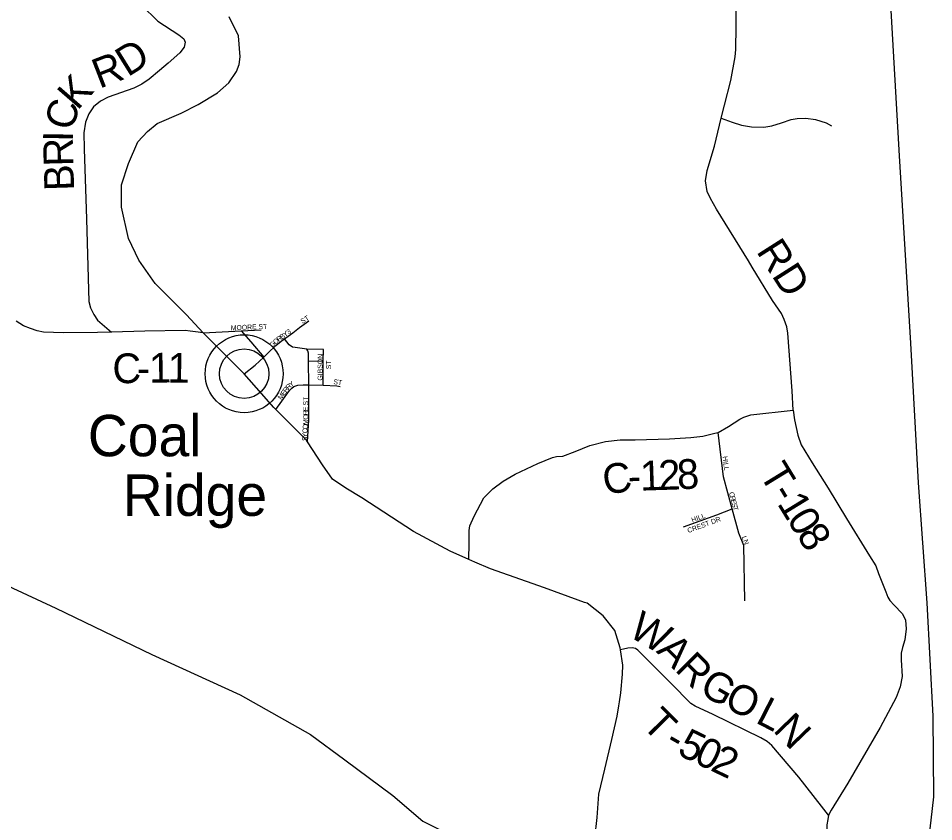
# Model space of a CAD drawing. Extents: x -22 to 431, y -18 to 160.
# Drawn here: x 322.192 to 323.94, y 149.867 to 151.4 of the extents above; entities that cross this region are included whole.
import ezdxf

# ---------------------------------------------------------------- set-up
doc = ezdxf.new("R2010")
doc.units = 0
for name, color, linetype in [('GM_X_Adjacent_County', 7, 'Continuous'), ('GM_X_Adjacent_County_Text', 7, 'Continuous'), ('GM_X_City_Street', 7, 'Continuous'), ('GM_X_City_Street_Text', 7, 'Continuous'), ('GM_X_County_Road', 7, 'Continuous'), ('GM_X_County_ROW', 7, 'Continuous'), ('GM_X_County_Subdivision', 7, 'Continuous'), ('GM_X_Minor_River_Text', 7, 'Continuous'), ('GM_X_Rail_Line', 7, 'Continuous'), ('GM_X_Township_Road', 7, 'Continuous'), ('GM_X_Township_ROW', 7, 'Continuous')]:
    doc.layers.add(name, color=color, linetype=linetype)

msp = doc.modelspace()

# ---------------------------------------------------------------- linework, layer by layer
at = {"layer": 'GM_X_Adjacent_County_Text'}
for points in [[(323.5933, 150.9254), (323.586, 150.9372), (323.525, 151.0361), (323.5136, 151.0562), (323.5075, 151.0698), (323.5045, 151.0903), (323.5075, 151.1097), (323.5211, 151.1564), (323.5344, 151.2095), (323.5407, 151.2346), (323.5524, 151.2816), (323.5607, 151.3268), (323.5622, 151.3408), (323.5629, 151.3848), (323.5629, 151.4307)], [(323.6719, 150.6523), (323.6696, 150.6895), (323.6611, 150.7992), (323.6592, 150.8117), (323.6543, 150.8253), (323.6494, 150.8371), (323.6323, 150.8617), (323.5933, 150.9254)], [(322.5453, 150.8003), (322.5304, 150.8018), (322.5202, 150.8031), (322.5107, 150.8045), (322.4338, 150.8031), (322.3702, 150.8016), (322.3437, 150.8007), (322.2785, 150.7999), (322.2402, 150.8015), (322.2285, 150.8036), (322.2155, 150.8083), (322.2022, 150.8134), (322.188, 150.8226)], [(323.0523, 150.3676), (323.053, 150.3987), (323.0533, 150.423), (323.0541, 150.4318), (323.0624, 150.4504), (323.0813, 150.4853), (323.098, 150.5024), (323.118, 150.5172), (323.1411, 150.5301), (323.1839, 150.5507), (323.2123, 150.5621), (323.2198, 150.564), (323.2319, 150.5648), (323.2554, 150.5736), (323.2834, 150.585), (323.3133, 150.5926), (323.3414, 150.5961), (323.3698, 150.5961), (323.4353, 150.5977), (323.4765, 150.6005), (323.4993, 150.6028), (323.522, 150.6085), (323.5282, 150.6098), (323.5481, 150.6211), (323.5697, 150.6351), (323.5772, 150.6393), (323.5905, 150.6435), (323.6719, 150.6523)]]:
    msp.add_lwpolyline(points, dxfattribs=at)
at = {"layer": 'GM_X_County_Road'}
msp.add_lwpolyline([(323.5344, 151.2095), (323.5553, 151.2023), (323.5731, 151.1964), (323.592, 151.1931), (323.6159, 151.1925), (323.6306, 151.1953), (323.6492, 151.2008), (323.6677, 151.207), (323.6794, 151.209), (323.696, 151.2095), (323.7142, 151.2073), (323.7343, 151.201), (323.7446, 151.1947)], dxfattribs=at)
at = {"layer": 'GM_X_County_ROW'}
for points in [[(323.2735, 150.2855), (323.2609, 150.2901), (323.1969, 150.3135), (323.0935, 150.3494), (323.0637, 150.3626), (323.0523, 150.3676), (323.0171, 150.3832), (322.9468, 150.4209), (322.8482, 150.4853), (322.8174, 150.5034), (322.7923, 150.5208), (322.7732, 150.5484), (322.7443, 150.5919), (322.7423, 150.595), (322.684, 150.6539), (322.6802, 150.6577), (322.6235, 150.722), (322.5539, 150.7912), (322.5453, 150.8003), (322.5133, 150.8343), (322.4539, 150.894), (322.4223, 150.9387), (322.4027, 150.98), (322.3892, 151.0396), (322.3891, 151.0825), (322.4029, 151.1232), (322.4207, 151.1642), (322.4388, 151.1843), (322.4574, 151.1992), (322.5035, 151.2191), (322.5354, 151.2357), (322.5724, 151.2578), (322.5944, 151.2768), (322.6088, 151.2988), (322.6141, 151.3121), (322.6159, 151.3265), (322.6129, 151.3667), (322.595, 151.4031)], [(322.1172, 150.3424), (322.2643, 150.2747), (322.4472, 150.1863), (322.6156, 150.1093), (322.7502, 150.0336), (322.816, 149.9854), (322.9073, 149.9171), (322.9648, 149.8683), (323.0568, 149.8221), (323.0865, 149.8101), (323.1193, 149.7957), (323.1226, 149.7951), (323.2065, 149.7788), (323.2897, 149.7606)], [(323.3389, 150.0883), (323.3401, 150.0961), (323.3426, 150.1129), (323.3455, 150.1486), (323.3462, 150.1661), (323.342, 150.1951), (323.3415, 150.1991), (323.3311, 150.2321), (323.3086, 150.2597), (323.2782, 150.2839), (323.2735, 150.2855)], [(323.2905, 149.7801), (323.2928, 149.8358), (323.2972, 149.8753), (323.3008, 149.9197), (323.312, 149.9676), (323.3255, 150.0243), (323.3359, 150.0684), (323.3389, 150.0883)]]:
    msp.add_lwpolyline(points, dxfattribs=at)
at = {"layer": 'GM_X_Minor_River_Text'}
for points in [[(322.4277, 151.4253), (322.4589, 151.3948), (322.4987, 151.3686), (322.5083, 151.3608), (322.5111, 151.3544), (322.509, 151.3452), (322.5009, 151.3344), (322.4785, 151.3143), (322.4617, 151.3007), (322.4423, 151.2841), (322.4284, 151.2743), (322.413, 151.2668), (322.4128, 151.2667)], [(322.4128, 151.2667), (322.3641, 151.25), (322.3495, 151.2418), (322.3356, 151.2313), (322.3271, 151.2178), (322.3206, 151.2022), (322.3172, 151.1816), (322.3181, 151.1509), (322.3223, 151.017), (322.3269, 150.8599), (322.3302, 150.8478), (322.3365, 150.8347), (322.3438, 150.8242), (322.3702, 150.8016)], [(323.6719, 150.6523), (323.6742, 150.6341), (323.6806, 150.6049), (323.6867, 150.5864), (323.7079, 150.5519), (323.7387, 150.5037), (323.7736, 150.4457), (323.8175, 150.3748), (323.8293, 150.3551), (323.8346, 150.3407), (323.8487, 150.3058), (323.8525, 150.2956), (323.8559, 150.2895), (323.8646, 150.2804), (323.8794, 150.2645), (323.8838, 150.2573), (323.8858, 150.252), (323.887, 150.235), (323.8847, 150.2141), (323.8806, 150.1997), (323.8779, 150.1887), (323.8776, 150.1758), (323.8795, 150.1443), (323.8757, 150.1245), (323.8685, 150.1044), (323.8375, 150.0467), (323.7759, 149.9404), (323.7441, 149.8895), (323.7392, 149.8797)], [(323.7392, 149.8797), (323.7256, 149.8971), (323.6824, 149.952), (323.6308, 150.0127), (323.6221, 150.0202), (323.61, 150.0274), (323.5187, 150.0717), (323.4842, 150.0876), (323.4762, 150.0929), (323.4383, 150.1315), (323.3997, 150.1698), (323.375, 150.1948), (323.3709, 150.1978), (323.3644, 150.1989), (323.3561, 150.1985), (323.342, 150.1951)], [(323.7392, 149.8797), (323.7377, 149.8713), (323.7358, 149.8615), (323.7351, 149.8387), (323.7321, 149.8091), (323.7298, 149.8008), (323.7284, 149.7951), (323.7272, 149.7875), (323.7268, 149.7583), (323.7266, 149.7514), (323.7213, 149.5557)]]:
    msp.add_lwpolyline(points, dxfattribs=at)
at = {"layer": 'GM_X_Rail_Line'}
msp.add_lwpolyline([(323.7541, 149.3438), (323.7718, 149.3859), (323.8142, 149.4956), (323.8253, 149.5261), (323.8788, 149.6629), (323.8836, 149.6785), (323.906, 149.7408), (323.9176, 149.7784), (323.9303, 149.8316), (323.9399, 149.9149), (323.9389, 150.0683), (323.9274, 150.2851), (323.911, 150.5141), (323.8962, 150.7806), (323.8747, 151.1376), (323.8507, 151.5599)], dxfattribs=at)
at = {"layer": 'GM_X_Township_Road'}
for radius in [0.0744, 0.0472]:
    msp.add_circle((322.6235, 150.722), radius, dxfattribs=at)
at = {"layer": 'GM_X_Township_ROW'}
for points in [[(322.6235, 150.722), (322.6443, 150.7382), (322.661, 150.7537), (322.6695, 150.7616), (322.6842, 150.7761), (322.694, 150.7841), (322.7004, 150.7888), (322.703, 150.7907), (322.7166, 150.7999), (322.7294, 150.8102), (322.7471, 150.8229)], [(322.5453, 150.8003), (322.6177, 150.8039), (322.6563, 150.8059)], [(322.6177, 150.8039), (322.6364, 150.7829), (322.661, 150.7537)], [(322.7443, 150.5919), (322.747, 150.6339), (322.7467, 150.7007), (322.7465, 150.7452), (322.7464, 150.761), (322.7453, 150.7659), (322.7433, 150.7686), (322.721, 150.7718), (322.7157, 150.7725), (322.7096, 150.7771), (322.7004, 150.7888)], [(322.7742, 150.6999), (322.7746, 150.7459), (322.7748, 150.7681), (322.7433, 150.7686)], [(322.7746, 150.7459), (322.7465, 150.7452)], [(322.684, 150.6539), (322.7102, 150.6902), (322.7143, 150.6944), (322.7185, 150.6978), (322.7257, 150.7001), (322.7359, 150.701), (322.7395, 150.7009)], [(322.7395, 150.7009), (322.7397, 150.7009), (322.7467, 150.7007), (322.7742, 150.6999), (322.8003, 150.6992), (322.8071, 150.6977)], [(323.5791, 150.2884), (323.5773, 150.3939), (323.5679, 150.4178), (323.5552, 150.4643), (323.5386, 150.525), (323.5282, 150.6098)], [(323.4625, 150.43), (323.5257, 150.453), (323.5552, 150.4643)]]:
    msp.add_lwpolyline(points, dxfattribs=at)

# ---------------------------------------------------------------- texts
at = {"layer": 'GM_X_Adjacent_County'}
for s, p in [('Coal', (322.3251, 150.5645)), ('Ridge', (322.3917, 150.4508))]:
    msp.add_text(s, height=0.07891, rotation=0, dxfattribs=at).set_placement(p)
at = {"layer": 'GM_X_City_Street'}
for s, height, rotation, p in [('RD', 0.05682, 302.5098, (323.6002, 150.9557)), ('C', 0.0568, 1.0226, (322.3725, 150.7035)), ('1', 0.0568, 0.9263, (322.4425, 150.7047)), ('1', 0.0568, 359.0164, (322.477, 150.7053)), ('-', 0.0568, 0.9992, (322.4192, 150.7043)), ('C', 0.0568, 9.2948, (323.3126, 150.4905)), ('1', 0.0568, 1.9414, (323.3801, 150.4988)), ('2', 0.0568, 1.9462, (323.4151, 150.4999)), ('8', 0.0568, 2.8385, (323.451, 150.5012)), ('-', 0.0568, 2.1939, (323.3568, 150.4979))]:
    msp.add_text(s, height=height, rotation=rotation, dxfattribs=at).set_placement(p)
at = {"layer": 'GM_X_City_Street_Text'}
for s, rotation, p in [('D', 31.9581, (322.4012, 151.2874)), ('R', 21.1476, (322.3472, 151.2654)), ('K', 49.1249, (322.3054, 151.2229)), ('C', 74.6904, (322.2962, 151.1837)), ('I', 89.4302, (322.2965, 151.1642)), ('R', 91.5067, (322.2977, 151.1181)), ('B', 91.741, (322.2991, 151.0715)), ('T', 301.4525, (323.6056, 150.5306)), ('-', 301.4551, (323.6278, 150.4943)), ('1', 301.4984, (323.64, 150.4744)), ('0', 301.6451, (323.6583, 150.4444)), ('8', 302.1899, (323.677, 150.4141)), ('W', 329.6052, (323.3548, 150.2226)), ('A', 315.0386, (323.4086, 150.1916)), ('R', 315.0304, (323.444, 150.1563)), ('G', 329.9828, (323.4898, 150.1135)), ('O', 334.3347, (323.5372, 150.0863)), ('L', 332.8772, (323.5977, 150.0571)), ('T', 314.8455, (323.3809, 150.0501)), ('N', 313.9361, (323.6316, 150.0407)), ('5', 334.2366, (323.4481, 149.9963)), ('-', 330.1625, (323.4239, 150.01)), ('0', 334.4996, (323.4798, 149.981)), ('2', 334.5917, (323.5115, 149.9659))]:
    msp.add_text(s, height=0.0568, rotation=rotation, dxfattribs=at).set_placement(p)
at = {"layer": 'GM_X_County_Subdivision'}
for s, rotation, p in [('ST', 32.7431, (322.7348, 150.8169)), ('MOORE ST', 2.4588, (322.5982, 150.8047)), ('R', 36.6076, (322.6896, 150.7826)), ('B', 36.0684, (322.6956, 150.787)), ('Y', 34.8541, (322.7016, 150.7914)), ('3', 34.9503, (322.7084, 150.7962)), ('G', 47.0868, (322.6777, 150.7716)), ('O', 38.8373, (322.6832, 150.7774)), ('GIBSON', 90, (322.7732, 150.7089)), ('ST', 90, (322.7894, 150.7305)), ('Y', 34.2114, (322.7131, 150.6959)), ('ST', 352.865, (322.7934, 150.7022)), ('E', 54.4734, (322.7002, 150.6796)), ('R', 54.3494, (322.7041, 150.6851)), ('R', 45.2232, (322.7082, 150.6908)), ('M', 54.4708, (322.6944, 150.6715)), ('ST', 90, (322.7457, 150.6614)), ('E', 89.9956, (322.7457, 150.6504)), ('R', 89.994, (322.7457, 150.6429)), ('M', 86.6464, (322.7451, 150.6239)), ('O', 89.4861, (322.7457, 150.6344)), ('C', 86.5979, (322.7441, 150.6081)), ('O', 86.6374, (322.7446, 150.6156)), ('S', 86.6111, (322.7433, 150.5932)), ('Y', 86.6374, (322.7437, 150.5998)), ('HILL', 277.1275, (323.5366, 150.5641)), ('C', 284.1835, (323.549, 150.4951)), ('R', 284.195, (323.5509, 150.4878)), ('E', 284.1887, (323.5527, 150.4806)), ('S', 284.1887, (323.5543, 150.4741)), ('T', 285.8553, (323.5561, 150.4673)), ('CREST DR', 20.3522, (323.4716, 150.4178)), ('HILL', 20.1333, (323.4793, 150.4379)), ('LN', 291.2529, (323.5731, 150.4103))]:
    msp.add_text(s, height=0.00947, rotation=rotation, dxfattribs=at).set_placement(p)

doc.saveas('drawing.dxf')
